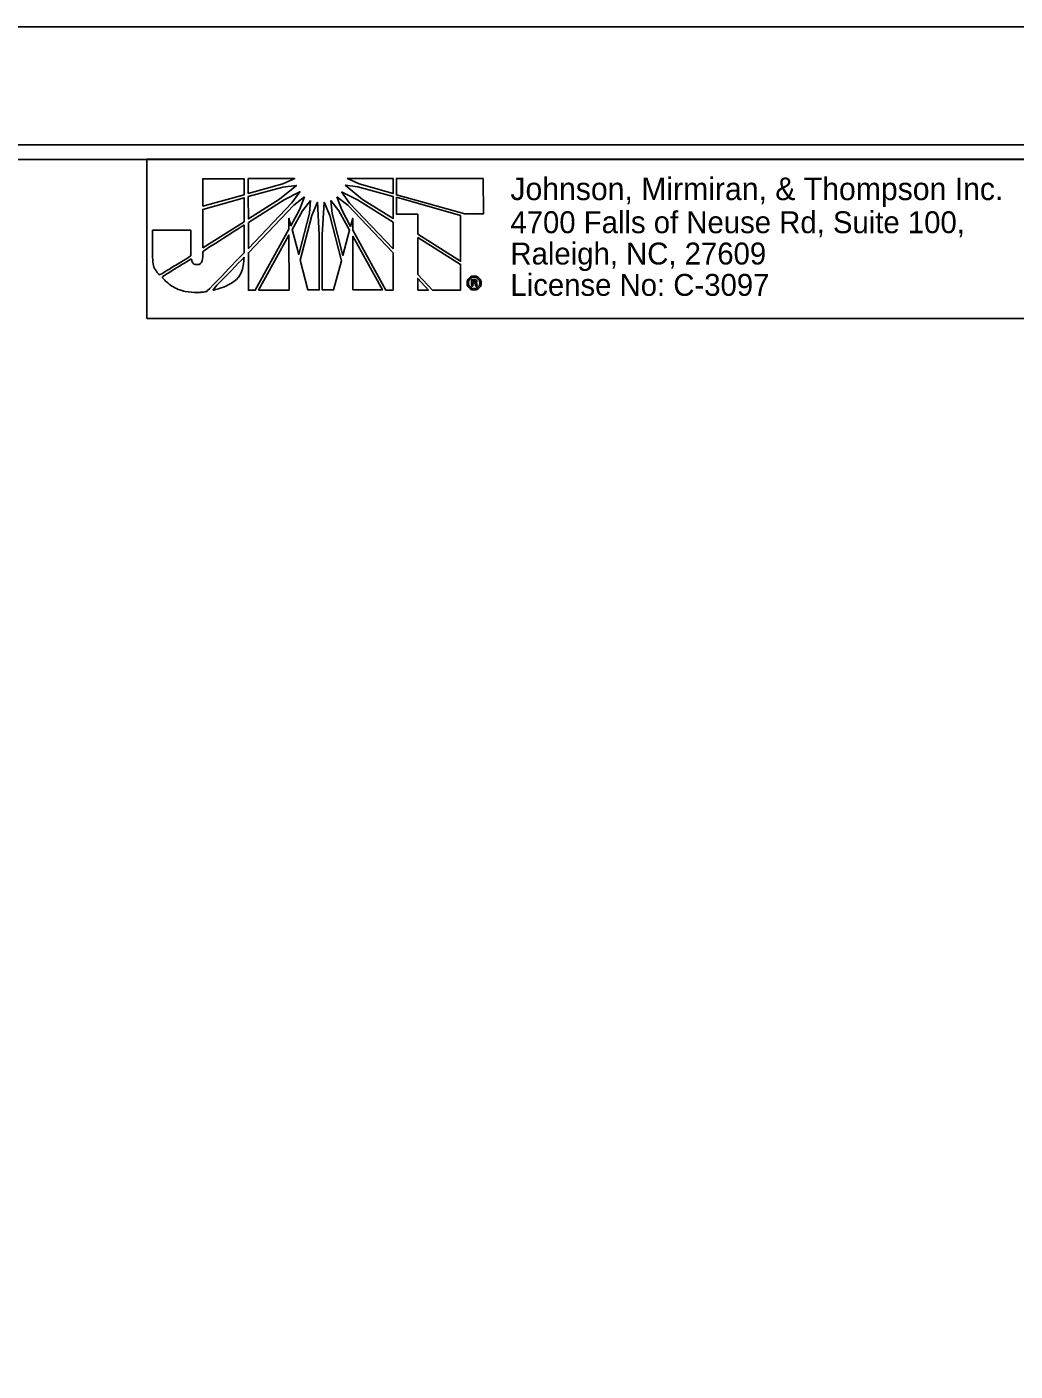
# Model space of a CAD drawing. Extents: x 1640342 to 1730599, y 538663 to 843747.
# Drawn here: x 1730099.93 to 1730133.49, y 538836.58 to 538882.22 of the extents above; entities that cross this region are included whole.
import ezdxf

# ---------------------------------------------------------------- set-up
doc = ezdxf.new("R2010")
doc.units = 0
for name, color, linetype in [('Prop Dimension Text', 7, 'Continuous'), ('Sheet Plan CELL', 7, 'Continuous'), ('Sheet Plot Border Inside CELL', 7, 'Continuous'), ('Sheet Plot Border Outside CELL', 7, 'Continuous')]:
    doc.layers.add(name, color=color, linetype=linetype)

msp = doc.modelspace()

# ---------------------------------------------------------------- linework, layer by layer
at = {"layer": 'Prop Dimension Text'}
for p, q in [((1730107.302, 538877.058), (1730105.899, 538877.057)), ((1730105.899, 538877.057), (1730105.9, 538876.126)), ((1730107.302, 538876.517), (1730107.302, 538877.058)), ((1730109.027, 538877.067), (1730107.448, 538877.065)), ((1730107.448, 538877.065), (1730107.448, 538876.563)), ((1730107.448, 538876.563), (1730108.624, 538876.888)), ((1730108.624, 538876.779), (1730107.448, 538876.454)), ((1730108.502, 538876.363), (1730109.082, 538876.835)), ((1730108.624, 538876.888), (1730109.027, 538877.067)), ((1730109.082, 538876.835), (1730108.624, 538876.779)), ((1730110.736, 538876.837), (1730111.324, 538876.356)), ((1730111.169, 538876.782), (1730110.736, 538876.837)), ((1730112.37, 538877.063), (1730110.814, 538877.069)), ((1730110.814, 538877.069), (1730111.208, 538876.884)), ((1730112.37, 538876.452), (1730111.169, 538876.782)), ((1730111.208, 538876.884), (1730112.37, 538876.558)), ((1730112.37, 538876.558), (1730112.37, 538877.063)), ((1730115.428, 538877.073), (1730112.479, 538877.07)), ((1730112.479, 538877.07), (1730112.479, 538876.528)), ((1730115.43, 538875.864), (1730115.428, 538877.073)), ((1730105.9, 538876.126), (1730107.302, 538876.517)), ((1730107.302, 538876.415), (1730105.9, 538876.02)), ((1730107.303, 538875.602), (1730107.302, 538876.415)), ((1730107.448, 538876.454), (1730107.449, 538875.695)), ((1730107.449, 538875.695), (1730108.502, 538876.363)), ((1730108.664, 538876.347), (1730107.449, 538875.572)), ((1730109.198, 538876.618), (1730108.664, 538876.347)), ((1730108.928, 538876.238), (1730109.198, 538876.618)), ((1730109.361, 538876.449), (1730108.988, 538876.162)), ((1730109.19, 538876), (1730109.361, 538876.449)), ((1730109.562, 538876.324), (1730109.285, 538875.967)), ((1730109.523, 538875.891), (1730109.562, 538876.324)), ((1730109.794, 538876.262), (1730109.602, 538875.813)), ((1730109.855, 538875.155), (1730109.794, 538876.262)), ((1730110.025, 538876.262), (1730109.954, 538875.155)), ((1730110.211, 538875.813), (1730110.025, 538876.262)), ((1730110.25, 538876.325), (1730110.296, 538875.876)), ((1730110.521, 538875.969), (1730110.25, 538876.325)), ((1730110.449, 538876.45), (1730110.621, 538876.001)), ((1730110.822, 538876.163), (1730110.449, 538876.45)), ((1730110.613, 538876.619), (1730110.884, 538876.233)), ((1730111.155, 538876.349), (1730110.613, 538876.619)), ((1730112.362, 538875.584), (1730111.155, 538876.349)), ((1730111.324, 538876.356), (1730112.362, 538875.709)), ((1730112.362, 538875.709), (1730112.37, 538876.452)), ((1730112.479, 538876.528), (1730112.479, 538876.512)), ((1730112.479, 538876.512), (1730114.802, 538875.864)), ((1730112.479, 538876.429), (1730112.479, 538876.42)), ((1730114.654, 538875.81), (1730112.479, 538876.429)), ((1730112.479, 538876.42), (1730112.48, 538875.855)), ((1730105.9, 538876.02), (1730105.901, 538874.712)), ((1730107.45, 538874.697), (1730108.928, 538876.238)), ((1730108.988, 538876.162), (1730107.45, 538874.549)), ((1730108.896, 538875.465), (1730109.19, 538876)), ((1730109.285, 538875.967), (1730108.936, 538875.333)), ((1730109.161, 538874.49), (1730109.523, 538875.891)), ((1730109.602, 538875.813), (1730109.208, 538874.296)), ((1730110.615, 538874.274), (1730110.211, 538875.813)), ((1730110.296, 538875.876), (1730110.661, 538874.459)), ((1730110.885, 538875.311), (1730110.521, 538875.969)), ((1730110.621, 538876.001), (1730110.922, 538875.443)), ((1730112.363, 538874.539), (1730110.822, 538876.163)), ((1730110.884, 538876.233), (1730112.363, 538874.685)), ((1730112.48, 538875.855), (1730113.2, 538875.855)), ((1730113.2, 538875.855), (1730113.201, 538875.182)), ((1730114.655, 538874.261), (1730114.654, 538875.81)), ((1730114.802, 538875.864), (1730115.43, 538875.864)), ((1730105.901, 538874.712), (1730107.303, 538875.602)), ((1730107.449, 538875.572), (1730107.45, 538874.697)), ((1730107.683, 538873.276), (1730108.827, 538875.349)), ((1730108.827, 538875.349), (1730108.826, 538875.719)), ((1730108.826, 538875.719), (1730108.896, 538875.465)), ((1730108.936, 538875.333), (1730109.161, 538874.49)), ((1730110.922, 538875.443), (1730110.994, 538875.721)), ((1730110.994, 538875.721), (1730110.994, 538875.311)), ((1730112.363, 538874.685), (1730112.362, 538875.584)), ((1730108.827, 538875.147), (1730107.792, 538873.276)), ((1730108.838, 538873.277), (1730108.827, 538875.147)), ((1730109.857, 538873.284), (1730109.855, 538875.155)), ((1730109.954, 538875.155), (1730109.956, 538873.285)), ((1730110.661, 538874.459), (1730110.885, 538875.311)), ((1730110.994, 538875.311), (1730112.116, 538873.28)), ((1730112.001, 538873.287), (1730110.994, 538875.11)), ((1730110.994, 538875.11), (1730110.996, 538873.286)), ((1730113.201, 538875.182), (1730114.655, 538874.261)), ((1730113.201, 538875.066), (1730113.202, 538873.811)), ((1730114.655, 538874.153), (1730113.201, 538875.066)), ((1730107.45, 538874.549), (1730107.451, 538873.275)), ((1730112.364, 538873.28), (1730112.363, 538874.539)), ((1730109.208, 538874.296), (1730109.472, 538873.284)), ((1730110.345, 538873.285), (1730110.615, 538874.274)), ((1730114.656, 538873.282), (1730114.655, 538874.153)), ((1730113.202, 538873.811), (1730113.705, 538873.281)), ((1730113.566, 538873.281), (1730113.202, 538873.674)), ((1730113.202, 538873.674), (1730113.202, 538873.281)), ((1730115.025, 538873.629), (1730115.113, 538873.63)), ((1730115.026, 538873.415), (1730115.025, 538873.629)), ((1730115.113, 538873.589), (1730115.074, 538873.589)), ((1730115.074, 538873.589), (1730115.074, 538873.538)), ((1730115.074, 538873.538), (1730115.113, 538873.538)), ((1730115.113, 538873.756), (1730115.113, 538873.711)), ((1730115.113, 538873.711), (1730115.113, 538873.756)), ((1730115.113, 538873.63), (1730115.113, 538873.589)), ((1730115.113, 538873.589), (1730115.113, 538873.63)), ((1730115.113, 538873.63), (1730115.127, 538873.63)), ((1730115.119, 538873.589), (1730115.113, 538873.589)), ((1730115.113, 538873.538), (1730115.113, 538873.499)), ((1730115.113, 538873.499), (1730115.113, 538873.538)), ((1730115.113, 538873.538), (1730115.115, 538873.538)), ((1730107.451, 538873.275), (1730107.683, 538873.276)), ((1730107.792, 538873.276), (1730108.838, 538873.277)), ((1730109.472, 538873.284), (1730109.857, 538873.284)), ((1730109.956, 538873.285), (1730110.345, 538873.285)), ((1730110.996, 538873.286), (1730112.001, 538873.287)), ((1730112.116, 538873.28), (1730112.364, 538873.28)), ((1730113.202, 538873.281), (1730113.566, 538873.281)), ((1730113.705, 538873.281), (1730114.656, 538873.282)), ((1730115.074, 538873.415), (1730115.026, 538873.415)), ((1730115.113, 538873.499), (1730115.074, 538873.499)), ((1730115.074, 538873.499), (1730115.074, 538873.415)), ((1730115.115, 538873.499), (1730115.113, 538873.499)), ((1730115.113, 538873.331), (1730115.114, 538873.284)), ((1730115.114, 538873.284), (1730115.113, 538873.331)), ((1730115.113, 538873.331), (1730115.115, 538873.331)), ((1730115.115, 538873.284), (1730115.114, 538873.284))]:
    msp.add_line(p, q, dxfattribs=at)
msp.add_lwpolyline([(1730104.001, 538872.31), (1730133.983, 538872.31), (1730133.983, 538877.721), (1730104.001, 538877.721)], close=True, dxfattribs=at)
for points in [[(1730105.9, 538876.126), (1730107.302, 538876.517), (1730107.302, 538877.058), (1730105.899, 538877.057), (1730105.9, 538876.126)], [(1730108.624, 538876.888), (1730109.027, 538877.067), (1730107.448, 538877.065), (1730107.448, 538876.563), (1730108.624, 538876.888)], [(1730107.448, 538876.454), (1730107.449, 538875.695), (1730108.502, 538876.363), (1730109.082, 538876.835), (1730108.624, 538876.779), (1730107.448, 538876.454)], [(1730110.736, 538876.837), (1730111.324, 538876.356), (1730112.362, 538875.709), (1730112.37, 538876.452), (1730111.169, 538876.782), (1730110.736, 538876.837)], [(1730111.208, 538876.884), (1730112.37, 538876.558), (1730112.37, 538877.063), (1730110.814, 538877.069), (1730111.208, 538876.884)], [(1730115.428, 538877.073), (1730112.479, 538877.07), (1730112.479, 538876.528), (1730112.479, 538876.512), (1730114.802, 538875.864), (1730115.43, 538875.864), (1730115.428, 538877.073)], [(1730105.901, 538874.712), (1730107.303, 538875.602), (1730107.302, 538876.415), (1730105.9, 538876.02), (1730105.901, 538874.712)], [(1730107.449, 538875.572), (1730107.45, 538874.697), (1730108.928, 538876.238), (1730109.198, 538876.618), (1730108.664, 538876.347), (1730107.449, 538875.572)], [(1730109.361, 538876.449), (1730108.988, 538876.162), (1730107.45, 538874.549), (1730107.451, 538873.275), (1730107.683, 538873.276), (1730108.827, 538875.349), (1730108.826, 538875.719), (1730108.896, 538875.465), (1730109.19, 538876), (1730109.361, 538876.449)], [(1730109.562, 538876.324), (1730109.285, 538875.967), (1730108.936, 538875.333), (1730109.161, 538874.49), (1730109.523, 538875.891), (1730109.562, 538876.324)], [(1730109.602, 538875.813), (1730109.208, 538874.296), (1730109.472, 538873.284), (1730109.857, 538873.284), (1730109.855, 538875.155), (1730109.794, 538876.262), (1730109.602, 538875.813)], [(1730110.025, 538876.262), (1730109.954, 538875.155), (1730109.956, 538873.285), (1730110.345, 538873.285), (1730110.615, 538874.274), (1730110.211, 538875.813), (1730110.025, 538876.262)], [(1730110.25, 538876.325), (1730110.296, 538875.876), (1730110.661, 538874.459), (1730110.885, 538875.311), (1730110.521, 538875.969), (1730110.25, 538876.325)], [(1730110.449, 538876.45), (1730110.621, 538876.001), (1730110.922, 538875.443), (1730110.994, 538875.721), (1730110.994, 538875.311), (1730112.116, 538873.28), (1730112.364, 538873.28), (1730112.363, 538874.539), (1730110.822, 538876.163), (1730110.449, 538876.45)], [(1730110.613, 538876.619), (1730110.884, 538876.233), (1730112.363, 538874.685), (1730112.362, 538875.584), (1730111.155, 538876.349), (1730110.613, 538876.619)], [(1730112.479, 538876.429), (1730112.479, 538876.42), (1730112.48, 538875.855), (1730113.2, 538875.855), (1730113.201, 538875.182), (1730114.655, 538874.261), (1730114.654, 538875.81), (1730112.479, 538876.429)], [(1730107.792, 538873.276), (1730108.838, 538873.277), (1730108.827, 538875.147), (1730107.792, 538873.276)], [(1730110.996, 538873.286), (1730112.001, 538873.287), (1730110.994, 538875.11), (1730110.996, 538873.286)], [(1730113.201, 538875.066), (1730113.202, 538873.811), (1730113.705, 538873.281), (1730114.656, 538873.282), (1730114.655, 538874.153), (1730113.201, 538875.066), (1730113.201, 538875.066)], [(1730113.202, 538873.281), (1730113.202, 538873.281), (1730113.566, 538873.281), (1730113.202, 538873.674), (1730113.202, 538873.281)], [(1730115.207, 538873.466), (1730115.207, 538873.454), (1730115.209, 538873.446), (1730115.209, 538873.438), (1730115.215, 538873.415), (1730115.17, 538873.415)]]:
    msp.add_lwpolyline(points, dxfattribs=at)
for points, degree in [([(1730105.7, 538874.144), (1730105.617, 538874.144), (1730105.545, 538874.19), (1730105.515, 538874.345), (1730105.515, 538874.345), (1730104.508, 538873.722), (1730104.508, 538873.722), (1730104.819, 538873.395), (1730105.314, 538873.201), (1730105.733, 538873.202), (1730105.842, 538873.202), (1730105.925, 538873.211), (1730106.041, 538873.235), (1730106.041, 538873.235), (1730107.304, 538874.542), (1730107.304, 538874.542), (1730107.304, 538874.542), (1730107.303, 538875.486), (1730107.303, 538875.486), (1730107.303, 538875.486), (1730105.901, 538874.594), (1730105.901, 538874.594), (1730105.901, 538874.239), (1730105.816, 538874.144), (1730105.7, 538874.144)], 3), ([(1730105.7, 538874.144), (1730105.617, 538874.144), (1730105.545, 538874.19), (1730105.515, 538874.345), (1730105.515, 538874.345), (1730104.508, 538873.722), (1730104.508, 538873.722), (1730104.819, 538873.395), (1730105.314, 538873.201), (1730105.733, 538873.202), (1730105.842, 538873.202), (1730105.925, 538873.211), (1730106.041, 538873.235), (1730106.041, 538873.235), (1730107.304, 538874.542), (1730107.304, 538874.542), (1730107.304, 538874.542), (1730107.303, 538875.486), (1730107.303, 538875.486), (1730107.303, 538875.486), (1730105.901, 538874.594), (1730105.901, 538874.594), (1730105.901, 538874.239), (1730105.816, 538874.144), (1730105.7, 538874.144)], 3), ([(1730105.497, 538875.313), (1730105.497, 538875.313), (1730104.199, 538875.312), (1730104.199, 538875.312), (1730104.199, 538875.312), (1730104.199, 538874.499), (1730104.199, 538874.499), (1730104.199, 538874.499), (1730104.199, 538874.414), (1730104.199, 538874.414), (1730104.2, 538874.159), (1730104.283, 538873.958), (1730104.432, 538873.789), (1730104.432, 538873.789), (1730105.498, 538874.438), (1730105.498, 538874.454), (1730105.498, 538874.454), (1730105.497, 538875.313), (1730105.497, 538875.313)], 3), ([(1730107.304, 538874.393), (1730107.304, 538874.393), (1730106.212, 538873.265), (1730106.212, 538873.265), (1730106.747, 538873.397), (1730107.279, 538873.752), (1730107.304, 538874.393)], 3), ([(1730115.114, 538873.284), (1730115.049, 538873.284), (1730114.993, 538873.308), (1730114.946, 538873.354), (1730114.899, 538873.399), (1730114.875, 538873.456), (1730114.875, 538873.522), (1730114.875, 538873.588), (1730114.899, 538873.645), (1730114.945, 538873.688), (1730114.992, 538873.733), (1730115.047, 538873.756), (1730115.113, 538873.756)], 3), ([(1730115.113, 538873.711), (1730115.06, 538873.711), (1730115.016, 538873.694), (1730114.979, 538873.659), (1730114.942, 538873.622), (1730114.922, 538873.575), (1730114.922, 538873.522), (1730114.922, 538873.469), (1730114.942, 538873.423), (1730114.979, 538873.386), (1730115.016, 538873.349), (1730115.061, 538873.331), (1730115.113, 538873.331)], 3), ([(1730115.113, 538873.756), (1730115.179, 538873.756), (1730115.236, 538873.733), (1730115.283, 538873.688), (1730115.33, 538873.645), (1730115.353, 538873.589), (1730115.353, 538873.522)], 3), ([(1730115.115, 538873.331), (1730115.168, 538873.331), (1730115.213, 538873.349), (1730115.25, 538873.386), (1730115.287, 538873.423), (1730115.306, 538873.47), (1730115.306, 538873.522), (1730115.306, 538873.575), (1730115.287, 538873.622), (1730115.25, 538873.659), (1730115.213, 538873.694), (1730115.168, 538873.711), (1730115.113, 538873.711)], 3), ([(1730115.115, 538873.538), (1730115.146, 538873.538), (1730115.162, 538873.548), (1730115.162, 538873.565), (1730115.162, 538873.581), (1730115.148, 538873.589), (1730115.119, 538873.589)], 3), ([(1730115.353, 538873.522), (1730115.353, 538873.456), (1730115.33, 538873.4), (1730115.285, 538873.353), (1730115.238, 538873.308), (1730115.182, 538873.284), (1730115.115, 538873.284)], 3), ([(1730115.127, 538873.63), (1730115.181, 538873.63), (1730115.209, 538873.608), (1730115.209, 538873.565), (1730115.209, 538873.546), (1730115.201, 538873.53), (1730115.184, 538873.518)], 3), ([(1730115.184, 538873.518), (1730115.197, 538873.511), (1730115.205, 538873.493), (1730115.207, 538873.466)], 2), ([(1730115.152, 538873.491), (1730115.146, 538873.495), (1730115.135, 538873.499), (1730115.115, 538873.499)], 2), ([(1730115.17, 538873.415), (1730115.164, 538873.427), (1730115.16, 538873.438), (1730115.16, 538873.454), (1730115.16, 538873.474), (1730115.158, 538873.485), (1730115.152, 538873.491)], 3)]:
    msp.add_open_spline(points, degree=degree, dxfattribs=at)
at = {"layer": 'Sheet Plan CELL'}
for points in [[(1729873.99, 538667.718), (1729873.985, 538877.713), (1730133.983, 538877.721), (1730133.985, 538847.708), (1730173.993, 538847.706), (1730173.993, 538667.718)], [(1730173.998, 538877.718), (1729873.99, 538877.718), (1729873.99, 538667.718), (1730173.993, 538667.718)]]:
    msp.add_lwpolyline(points, close=True, dxfattribs=at)
at = {"layer": 'Sheet Plot Border Inside CELL'}
msp.add_lwpolyline([(1729843.293, 538667.216), (1730176.49, 538667.218), (1730176.493, 538878.216), (1729843.293, 538878.216)], close=True, dxfattribs=at)
at = {"layer": 'Sheet Plot Border Outside CELL'}
msp.add_lwpolyline([(1729840.693, 538663.216), (1730177.393, 538663.216), (1730177.393, 538882.216), (1729840.693, 538882.216)], close=True, dxfattribs=at)

# ---------------------------------------------------------------- texts
at = {"layer": 'Prop Dimension Text'}
for s, height, p in [('Johnson, Mirmiran, & Thompson Inc.', 0.76607, (1730116.348, 538876.335)), ('4700 Falls of Neuse Rd, Suite 100, ', 0.74418, (1730116.348, 538875.211)), ('Raleigh, NC, 27609', 0.74418, (1730116.348, 538874.148)), ('License No: C-3097', 0.74418, (1730116.348, 538873.084))]:
    msp.add_text(s, height=height, rotation=360, dxfattribs=at).set_placement(p)

doc.saveas('drawing.dxf')
